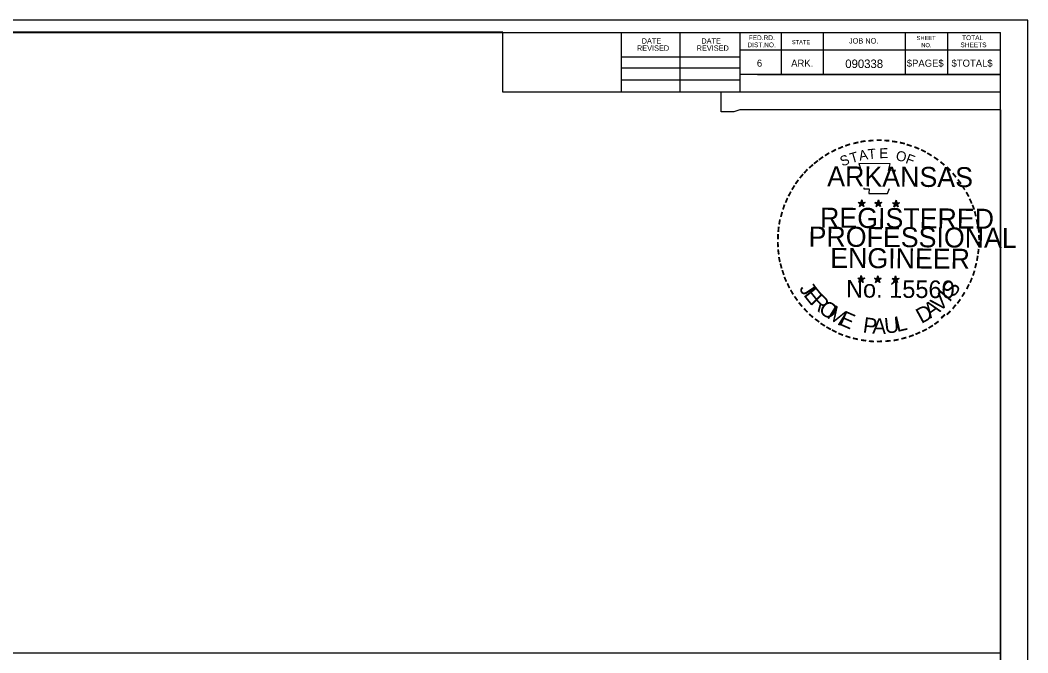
# Model space of a CAD drawing. Extents: x -1.3 to 32.1, y -0.2 to 20.7.
# Drawn here: x 15.42 to 32.07, y 10.29 to 20.75 of the extents above; entities that cross this region are included whole.
import ezdxf

# ---------------------------------------------------------------- set-up
doc = ezdxf.new("R2010")
doc.units = 0
for name, color, linetype in [('Level 1', 7, 'Continuous'), ('Level 24', 7, 'Continuous'), ('Level 62', 7, 'Continuous'), ('Level 63', 7, 'Continuous'), ('Level 63 Full', 7, 'Continuous'), ('R_Border', 7, 'Continuous')]:
    doc.layers.add(name, color=color, linetype=linetype)

msp = doc.modelspace()

# ---------------------------------------------------------------- linework, layer by layer
at = {"layer": 'Level 1'}
for p, q in [((-0.001, 20.545), (31.617, 20.545)), ((25.353, 19.557), (25.353, 20.545)), ((26.321, 19.557), (26.321, 20.545)), ((27.307, 20.545), (27.307, 19.557)), ((27.991, 20.545), (27.991, 19.851)), ((28.685, 20.545), (28.685, 19.851)), ((30.043, 20.545), (30.043, 19.851)), ((30.737, 20.545), (30.737, 19.851)), ((31.617, -0.001), (31.617, 20.545)), ((25.353, 20.143), (27.307, 20.143)), ((31.617, 20.251), (27.307, 20.251)), ((31.617, 20.253), (31.617, 20.253)), ((25.353, 19.957), (27.307, 19.957)), ((31.617, 19.851), (27.307, 19.851)), ((27.603, 19.851), (31.617, 19.851)), ((25.353, 19.763), (27.307, 19.763)), ((31.617, 19.557), (25.353, 19.557))]:
    msp.add_line(p, q, dxfattribs=at)
at = {"layer": 'Level 24'}
for p, q in [((23.392, 20.546), (0, 20.546)), ((23.392, 19.558), (23.392, 20.546)), ((27, 19.558), (23.392, 19.558)), ((27, 19.233), (27, 19.558)), ((27.212, 19.233), (27, 19.233)), ((27.308, 19.266), (27.212, 19.233)), ((31.618, 19.266), (27.308, 19.266)), ((31.618, 10.294), (31.618, 19.266)), ((0, 10.294), (31.618, 10.294))]:
    msp.add_line(p, q, dxfattribs=at)
at = {"layer": 'Level 62'}
for p, q in [((23.392, 20.546), (0, 20.546)), ((23.392, 19.558), (23.392, 20.546)), ((27, 19.558), (23.392, 19.558)), ((27, 19.233), (27, 19.558)), ((27.212, 19.233), (27, 19.233)), ((27.308, 19.266), (27.212, 19.233)), ((31.618, 19.266), (27.308, 19.266)), ((31.618, 10.294), (31.618, 19.266)), ((31.618, 0), (31.618, 10.294))]:
    msp.add_line(p, q, dxfattribs=at)
at = {"layer": 'Level 63'}
msp.add_lwpolyline([(-1.263, -0.2), (32.067, -0.2), (32.067, 20.746), (-1.263, 20.746)], close=True, dxfattribs=at)
at = {"layer": 'Level 63 Full'}
for p, q in [((29.264, 17.735), (29.323, 17.717)), ((29.264, 17.735), (29.307, 17.733)), ((29.264, 17.735), (29.307, 17.731)), ((29.264, 17.735), (29.302, 17.725)), ((29.264, 17.735), (29.302, 17.719)), ((29.264, 17.735), (29.302, 17.717)), ((29.264, 17.735), (29.302, 17.711)), ((29.288, 17.668), (29.323, 17.717)), ((29.288, 17.668), (29.302, 17.715)), ((29.288, 17.668), (29.307, 17.709)), ((29.288, 17.668), (29.309, 17.707)), ((29.288, 17.668), (29.315, 17.703)), ((29.288, 17.668), (29.323, 17.703)), ((29.288, 17.668), (29.323, 17.699)), ((29.323, 17.78), (29.315, 17.735)), ((29.323, 17.78), (29.315, 17.739)), ((29.323, 17.78), (29.319, 17.739)), ((29.323, 17.717), (29.323, 17.78)), ((29.323, 17.78), (29.333, 17.735)), ((29.323, 17.78), (29.331, 17.739)), ((29.323, 17.78), (29.325, 17.739)), ((29.38, 17.735), (29.323, 17.717)), ((29.358, 17.666), (29.323, 17.717)), ((29.358, 17.666), (29.323, 17.703)), ((29.358, 17.666), (29.323, 17.699)), ((29.38, 17.735), (29.327, 17.731)), ((29.358, 17.666), (29.327, 17.703)), ((29.38, 17.735), (29.333, 17.727)), ((29.38, 17.735), (29.333, 17.723)), ((29.358, 17.666), (29.333, 17.715)), ((29.358, 17.666), (29.333, 17.709)), ((29.358, 17.666), (29.339, 17.717)), ((29.38, 17.735), (29.341, 17.723)), ((29.38, 17.735), (29.347, 17.719)), ((29.38, 17.735), (29.349, 17.717)), ((29.539, 17.733), (29.598, 17.717)), ((29.539, 17.733), (29.582, 17.731)), ((29.539, 17.733), (29.582, 17.727)), ((29.539, 17.733), (29.582, 17.725)), ((29.539, 17.733), (29.58, 17.717)), ((29.539, 17.733), (29.58, 17.715)), ((29.539, 17.733), (29.58, 17.709)), ((29.564, 17.666), (29.598, 17.717)), ((29.564, 17.666), (29.582, 17.711)), ((29.564, 17.666), (29.582, 17.709)), ((29.564, 17.666), (29.584, 17.707)), ((29.564, 17.666), (29.59, 17.701)), ((29.564, 17.666), (29.598, 17.701)), ((29.564, 17.666), (29.598, 17.699)), ((29.598, 17.776), (29.59, 17.733)), ((29.598, 17.776), (29.59, 17.735)), ((29.598, 17.776), (29.592, 17.735)), ((29.598, 17.717), (29.598, 17.776)), ((29.598, 17.776), (29.608, 17.733)), ((29.598, 17.776), (29.606, 17.735)), ((29.598, 17.776), (29.6, 17.735)), ((29.655, 17.733), (29.598, 17.717)), ((29.633, 17.666), (29.598, 17.717)), ((29.633, 17.666), (29.598, 17.701)), ((29.633, 17.666), (29.598, 17.699)), ((29.655, 17.733), (29.604, 17.731)), ((29.633, 17.666), (29.604, 17.701)), ((29.655, 17.733), (29.608, 17.725)), ((29.655, 17.733), (29.608, 17.723)), ((29.633, 17.666), (29.608, 17.715)), ((29.633, 17.666), (29.608, 17.707)), ((29.633, 17.666), (29.615, 17.715)), ((29.655, 17.733), (29.617, 17.719)), ((29.655, 17.733), (29.623, 17.717)), ((29.655, 17.733), (29.625, 17.715)), ((29.831, 17.731), (29.89, 17.711)), ((29.831, 17.731), (29.878, 17.725)), ((29.831, 17.731), (29.874, 17.723)), ((29.831, 17.731), (29.874, 17.719)), ((29.831, 17.731), (29.872, 17.715)), ((29.831, 17.731), (29.872, 17.709)), ((29.831, 17.731), (29.872, 17.709)), ((29.853, 17.664), (29.89, 17.711)), ((29.853, 17.664), (29.874, 17.709)), ((29.853, 17.664), (29.878, 17.703)), ((29.853, 17.664), (29.878, 17.701)), ((29.853, 17.664), (29.89, 17.701)), ((29.853, 17.664), (29.886, 17.699)), ((29.853, 17.664), (29.894, 17.692)), ((29.89, 17.772), (29.88, 17.733)), ((29.89, 17.772), (29.886, 17.731)), ((29.89, 17.772), (29.886, 17.731)), ((29.89, 17.711), (29.89, 17.772)), ((29.89, 17.772), (29.902, 17.731)), ((29.89, 17.772), (29.898, 17.731)), ((29.89, 17.772), (29.894, 17.731)), ((29.947, 17.731), (29.89, 17.711)), ((29.923, 17.664), (29.89, 17.711)), ((29.923, 17.664), (29.89, 17.701)), ((29.923, 17.664), (29.89, 17.692)), ((29.947, 17.731), (29.896, 17.725)), ((29.923, 17.664), (29.896, 17.699)), ((29.947, 17.731), (29.902, 17.723)), ((29.947, 17.731), (29.902, 17.717)), ((29.923, 17.664), (29.902, 17.709)), ((29.923, 17.664), (29.902, 17.703)), ((29.923, 17.664), (29.906, 17.709)), ((29.947, 17.731), (29.91, 17.715)), ((29.947, 17.731), (29.912, 17.715)), ((29.947, 17.731), (29.919, 17.711)), ((29.256, 16.483), (29.315, 16.464)), ((29.256, 16.483), (29.298, 16.481)), ((29.256, 16.483), (29.296, 16.475)), ((29.256, 16.483), (29.296, 16.475)), ((29.256, 16.483), (29.296, 16.466)), ((29.256, 16.483), (29.296, 16.464)), ((29.256, 16.483), (29.296, 16.462)), ((29.315, 16.528), (29.302, 16.487)), ((29.315, 16.528), (29.307, 16.483)), ((29.315, 16.528), (29.309, 16.483)), ((29.315, 16.464), (29.315, 16.528)), ((29.315, 16.528), (29.323, 16.483)), ((29.315, 16.528), (29.323, 16.483)), ((29.315, 16.528), (29.315, 16.483)), ((29.372, 16.483), (29.315, 16.464)), ((29.372, 16.483), (29.319, 16.481)), ((29.372, 16.483), (29.323, 16.475)), ((29.372, 16.483), (29.323, 16.473)), ((29.372, 16.483), (29.331, 16.471)), ((29.372, 16.483), (29.335, 16.466)), ((29.372, 16.483), (29.339, 16.464)), ((29.531, 16.483), (29.59, 16.464)), ((29.531, 16.483), (29.574, 16.479)), ((29.531, 16.483), (29.574, 16.475)), ((29.531, 16.483), (29.574, 16.473)), ((29.531, 16.483), (29.572, 16.466)), ((29.531, 16.483), (29.572, 16.462)), ((29.531, 16.483), (29.572, 16.458)), ((29.59, 16.524), (29.58, 16.483)), ((29.59, 16.524), (29.582, 16.483)), ((29.59, 16.524), (29.584, 16.483)), ((29.59, 16.464), (29.59, 16.524)), ((29.59, 16.524), (29.598, 16.481)), ((29.59, 16.524), (29.598, 16.481)), ((29.59, 16.524), (29.59, 16.483)), ((29.645, 16.481), (29.59, 16.464)), ((29.645, 16.481), (29.596, 16.481)), ((29.645, 16.481), (29.598, 16.473)), ((29.645, 16.481), (29.598, 16.473)), ((29.645, 16.481), (29.606, 16.466)), ((29.645, 16.481), (29.613, 16.464)), ((29.645, 16.481), (29.615, 16.462)), ((29.882, 16.522), (29.872, 16.479)), ((29.882, 16.522), (29.874, 16.479)), ((29.882, 16.522), (29.878, 16.479)), ((29.882, 16.458), (29.882, 16.522)), ((29.882, 16.522), (29.89, 16.479)), ((29.882, 16.522), (29.89, 16.479)), ((29.882, 16.522), (29.882, 16.479)), ((29.276, 16.42), (29.315, 16.464)), ((29.276, 16.42), (29.296, 16.464)), ((29.276, 16.42), (29.298, 16.456)), ((29.276, 16.42), (29.3, 16.456)), ((29.276, 16.42), (29.315, 16.454)), ((29.276, 16.42), (29.307, 16.45)), ((29.276, 16.42), (29.315, 16.448)), ((29.347, 16.415), (29.311, 16.448)), ((29.347, 16.415), (29.315, 16.464)), ((29.347, 16.415), (29.315, 16.45)), ((29.347, 16.415), (29.317, 16.45)), ((29.347, 16.415), (29.323, 16.464)), ((29.347, 16.415), (29.323, 16.456)), ((29.347, 16.415), (29.331, 16.464)), ((29.551, 16.415), (29.59, 16.464)), ((29.551, 16.415), (29.574, 16.462)), ((29.551, 16.415), (29.574, 16.454)), ((29.551, 16.415), (29.576, 16.454)), ((29.551, 16.415), (29.582, 16.45)), ((29.551, 16.415), (29.59, 16.45)), ((29.551, 16.415), (29.59, 16.446)), ((29.623, 16.415), (29.588, 16.446)), ((29.623, 16.415), (29.59, 16.464)), ((29.623, 16.415), (29.59, 16.45)), ((29.623, 16.415), (29.592, 16.45)), ((29.623, 16.415), (29.598, 16.462)), ((29.623, 16.415), (29.598, 16.456)), ((29.623, 16.415), (29.606, 16.462)), ((29.823, 16.479), (29.882, 16.458)), ((29.823, 16.479), (29.866, 16.475)), ((29.823, 16.479), (29.866, 16.471)), ((29.823, 16.479), (29.863, 16.466)), ((29.823, 16.479), (29.863, 16.462)), ((29.823, 16.479), (29.861, 16.458)), ((29.823, 16.479), (29.861, 16.454)), ((29.845, 16.411), (29.882, 16.458)), ((29.845, 16.411), (29.863, 16.458)), ((29.845, 16.411), (29.866, 16.45)), ((29.845, 16.411), (29.87, 16.45)), ((29.845, 16.411), (29.874, 16.446)), ((29.845, 16.411), (29.88, 16.446)), ((29.845, 16.411), (29.882, 16.442)), ((29.914, 16.411), (29.88, 16.446)), ((29.914, 16.411), (29.88, 16.442)), ((29.939, 16.479), (29.882, 16.458)), ((29.914, 16.411), (29.882, 16.458)), ((29.914, 16.411), (29.886, 16.446)), ((29.939, 16.479), (29.888, 16.475)), ((29.939, 16.479), (29.89, 16.471)), ((29.939, 16.479), (29.89, 16.466)), ((29.914, 16.411), (29.89, 16.45)), ((29.914, 16.411), (29.894, 16.458)), ((29.914, 16.411), (29.896, 16.458)), ((29.939, 16.479), (29.902, 16.464)), ((29.939, 16.479), (29.904, 16.458)), ((29.939, 16.479), (29.906, 16.458))]:
    msp.add_line(p, q, dxfattribs=at)
for points in [[(29.276, 18.378), (29.317, 18.239)], [(29.855, 18.221), (29.88, 18.27), (29.764, 18.264), (29.79, 18.374), (29.276, 18.378)], [(29.356, 17.976), (29.356, 17.96), (29.447, 17.958), (29.439, 17.882), (29.747, 17.88), (29.78, 17.966)], [(29.323, 17.78), (29.358, 17.666), (29.264, 17.735), (29.38, 17.735), (29.288, 17.668), (29.323, 17.78)], [(29.598, 17.776), (29.633, 17.666), (29.539, 17.733), (29.655, 17.733), (29.564, 17.666), (29.598, 17.776)], [(29.89, 17.772), (29.923, 17.664), (29.831, 17.731), (29.947, 17.731), (29.853, 17.664), (29.89, 17.772)], [(29.315, 16.528), (29.347, 16.415), (29.256, 16.483), (29.372, 16.483), (29.276, 16.42), (29.315, 16.528)], [(29.59, 16.524), (29.623, 16.415), (29.531, 16.483), (29.645, 16.481), (29.551, 16.415), (29.59, 16.524)], [(29.882, 16.522), (29.914, 16.411), (29.823, 16.479), (29.939, 16.479), (29.845, 16.411), (29.882, 16.522)], [(30.647, 15.816), (30.639, 15.842), (30.688, 15.883)], [(30.684, 15.889), (30.692, 15.865), (30.643, 15.822)], [(30.692, 15.869), (30.643, 15.826)], [(30.692, 15.865), (30.645, 15.824)]]:
    msp.add_lwpolyline(points, dxfattribs=at)
for centre, radius in [((29.324, 17.716), 0.0285), ((29.324, 17.716), 0.0258), ((29.324, 17.716), 0.0239), ((29.324, 17.716), 0.0219), ((29.324, 17.716), 0.0191), ((29.324, 17.716), 0.0178), ((29.324, 17.716), 0.0164), ((29.324, 17.716), 0.0141), ((29.324, 17.716), 0.0124), ((29.324, 17.716), 0.0103), ((29.324, 17.716), 0.00819), ((29.324, 17.716), 0.00611), ((29.324, 17.716), 0.0049), ((29.324, 17.716), 0.00238), ((29.6, 17.714), 0.0285), ((29.6, 17.714), 0.0258), ((29.6, 17.714), 0.0239), ((29.6, 17.714), 0.0219), ((29.6, 17.714), 0.0191), ((29.6, 17.714), 0.0178), ((29.6, 17.714), 0.0164), ((29.6, 17.714), 0.0141), ((29.6, 17.714), 0.0124), ((29.6, 17.714), 0.0103), ((29.6, 17.714), 0.00819), ((29.6, 17.714), 0.00611), ((29.6, 17.714), 0.0049), ((29.6, 17.714), 0.00238), ((29.892, 17.71), 0.0285), ((29.892, 17.71), 0.0258), ((29.892, 17.71), 0.0239), ((29.892, 17.71), 0.0219), ((29.892, 17.71), 0.0191), ((29.892, 17.71), 0.0178), ((29.892, 17.71), 0.0164), ((29.892, 17.71), 0.0141), ((29.892, 17.71), 0.0124), ((29.892, 17.71), 0.0103), ((29.892, 17.71), 0.00819), ((29.892, 17.71), 0.00611), ((29.892, 17.71), 0.0049), ((29.892, 17.71), 0.00238), ((29.315, 16.464), 0.0285), ((29.315, 16.464), 0.0258), ((29.315, 16.464), 0.0239), ((29.315, 16.464), 0.0219), ((29.315, 16.464), 0.0191), ((29.315, 16.464), 0.0178), ((29.315, 16.464), 0.0164), ((29.59, 16.462), 0.0285), ((29.59, 16.462), 0.0258), ((29.59, 16.462), 0.0239), ((29.59, 16.462), 0.0219), ((29.59, 16.462), 0.0191), ((29.882, 16.458), 0.0285), ((29.882, 16.458), 0.0258), ((29.882, 16.458), 0.0239), ((29.315, 16.464), 0.0141), ((29.315, 16.464), 0.0124), ((29.315, 16.464), 0.0103), ((29.315, 16.464), 0.00819), ((29.315, 16.464), 0.00611), ((29.315, 16.464), 0.0049), ((29.315, 16.464), 0.00238), ((29.59, 16.462), 0.0178), ((29.59, 16.462), 0.0164), ((29.59, 16.462), 0.0141), ((29.59, 16.462), 0.0124), ((29.59, 16.462), 0.0103), ((29.59, 16.462), 0.00819), ((29.59, 16.462), 0.00611), ((29.59, 16.462), 0.0049), ((29.59, 16.462), 0.00238), ((29.882, 16.458), 0.0219), ((29.882, 16.458), 0.0191), ((29.882, 16.458), 0.0178), ((29.882, 16.458), 0.0164), ((29.882, 16.458), 0.0141), ((29.882, 16.458), 0.0124), ((29.882, 16.458), 0.0103), ((29.882, 16.458), 0.00819), ((29.882, 16.458), 0.00611), ((29.882, 16.458), 0.0049), ((29.882, 16.458), 0.00238)]:
    msp.add_circle(centre, radius, dxfattribs=at)

# ---------------------------------------------------------------- texts
at = {"layer": 'Level 1'}
for s, height, p in [('FED.RD.', 0.0782, (27.455, 20.417)), ('SHEET', 0.0684, (30.229, 20.417)), ('TOTAL', 0.0782, (30.981, 20.417)), ('REVISED', 0.0879, (25.609, 20.241)), ('DATE', 0.0879, (25.687, 20.359)), ('REVISED', 0.0879, (26.595, 20.241)), ('DATE', 0.0879, (26.673, 20.359)), ('DIST.NO.', 0.0782, (27.435, 20.299)), ('STATE', 0.0684, (28.167, 20.349)), ('JOB NO.', 0.0879, (29.112, 20.36)), ('NO.', 0.0684, (30.307, 20.299)), ('SHEETS', 0.0782, (30.953, 20.299)), ('6', 0.117, (27.591, 19.977)), ('ARK.', 0.1172, (28.157, 19.977)), ('090338', 0.14, (29.051, 19.956)), ('$PAGE$', 0.1172, (30.067, 19.977)), ('$TOTAL$', 0.1172, (30.806, 19.977))]:
    msp.add_text(s, height=height, dxfattribs=at).set_placement(p)
at = {"layer": 'Level 63 Full'}
for s, height, rotation, p in [('-', 0.264, 23.9096, (28.962, 18.523)), ('-', 0.264, 18.7785, (29.068, 18.568)), ('-', 0.264, 13.2326, (29.192, 18.606)), ('-', 0.264, 9.8217, (29.302, 18.633)), ('-', 0.264, 5.4992, (29.425, 18.649)), ('-', 0.264, 359.7886, (29.551, 18.661)), ('-', 0.264, 357.3454, (29.674, 18.657)), ('-', 0.264, 351.7641, (29.794, 18.647)), ('-', 0.264, 346.8073, (29.914, 18.629)), ('-', 0.264, 341.9386, (30.019, 18.6)), ('-', 0.264, 337.4575, (30.139, 18.564)), ('-', 0.264, 35.8341, (28.662, 18.347)), ('-', 0.264, 33.666, (28.758, 18.413)), ('-', 0.264, 28.3942, (28.858, 18.472)), ('S', 0.165, 21.1964, (29.001, 18.327)), ('T', 0.165, 16.006, (29.152, 18.382)), ('A', 0.165, 10.8156, (29.29, 18.423)), ('T', 0.165, 5.6252, (29.431, 18.449)), ('E', 0.165, 0.4347, (29.613, 18.466)), ('O', 0.165, 350.0539, (29.878, 18.431)), ('F', 0.165, 339.6731, (30.035, 18.39)), ('-', 0.264, 333.7235, (30.245, 18.521)), ('-', 0.264, 329.2433, (30.339, 18.472)), ('-', 0.264, 325.4651, (30.445, 18.409)), ('-', 0.264, 42.5646, (28.511, 18.217)), ('-', 0.264, 38.5531, (28.584, 18.284)), ('ARKANSAS', 0.3306, 359.6024, (28.752, 18.003)), ('-', 0.264, 320.1321, (30.545, 18.339)), ('-', 0.264, 315.181, (30.645, 18.258)), ('-', 0.264, 50.2166, (28.368, 18.06)), ('-', 0.264, 48.0254, (28.435, 18.139)), ('-', 0.264, 309.4821, (30.737, 18.166)), ('-', 0.264, 57.673, (28.246, 17.876)), ('-', 0.264, 53.8349, (28.299, 17.966)), ('-', 0.264, 306.2546, (30.82, 18.066)), ('-', 0.231, 303.2777, (30.902, 17.97)), ('-', 0.264, 67.3767, (28.152, 17.676)), ('-', 0.264, 62.4738, (28.195, 17.776)), ('-', 0.264, 299.2708, (30.953, 17.87)), ('-', 0.264, 71.9969, (28.113, 17.572)), ('REGISTERED', 0.3306, 359.6024, (28.633, 17.319)), ('-', 0.264, 294.2652, (31.006, 17.768)), ('-', 0.264, 290.1752, (31.051, 17.676)), ('-', 0.264, 75.0634, (28.081, 17.454)), ('-', 0.264, 284.7257, (31.085, 17.578)), ('-', 0.264, 84.7887, (28.044, 17.223)), ('-', 0.264, 80.8037, (28.056, 17.338)), ('PROFESSIONAL', 0.33055, 359.6024, (28.444, 17.007)), ('-', 0.264, 280.1517, (31.118, 17.454)), ('-', 0.264, 276.1986, (31.147, 17.327)), ('-', 0.264, 88.6646, (28.04, 17.107)), ('-', 0.264, 273.9325, (31.155, 17.207)), ('-', 0.264, 93.7983, (28.044, 16.987)), ('ENGINEER', 0.3306, 359.6024, (28.801, 16.654)), ('-', 0.264, 269.5431, (31.159, 17.105)), ('-', 0.264, 98.5503, (28.056, 16.874)), ('-', 0.264, 101.3173, (28.074, 16.754)), ('-', 0.264, 260.5977, (31.141, 16.887)), ('-', 0.264, 263.1196, (31.155, 16.995)), ('-', 0.264, 105.0602, (28.103, 16.656)), ('-', 0.264, 255.365, (31.122, 16.774)), ('-', 0.264, 108.6898, (28.138, 16.554)), ('-', 0.264, 113.6667, (28.178, 16.452)), ('-', 0.264, 247.4911, (31.057, 16.542)), ('-', 0.264, 252.4705, (31.094, 16.654)), ('-', 0.264, 115.3313, (28.229, 16.35)), ('J', 0.255, 303.9209, (28.28, 16.311)), ('E', 0.255, 308.618, (28.351, 16.204)), ('No. 15560', 0.2909, 359.6024, (29.062, 16.165)), ('S', 0.255, 53.5227, (30.835, 16.149)), ('-', 0.264, 244.2221, (31.01, 16.44)), ('-', 0.264, 120.0495, (28.287, 16.252)), ('-', 0.264, 125.4958, (28.354, 16.16)), ('R', 0.255, 314.7784, (28.458, 16.074)), ('V', 0.255, 41.4844, (30.603, 15.916)), ('I', 0.255, 49.9999, (30.772, 16.076)), ('-', 0.264, 238.6736, (30.945, 16.318)), ('-', 0.264, 130.3205, (28.427, 16.069)), ('-', 0.264, 133.8262, (28.513, 15.979)), ('O', 0.255, 321.6761, (28.593, 15.943)), ('M', 0.255, 328.1357, (28.734, 15.836)), ('D', 0.255, 28.5809, (30.307, 15.726)), ('A', 0.255, 34.8903, (30.457, 15.811)), ('-', 0.264, 233.4476, (30.804, 16.12)), ('-', 0.264, 233.4476, (30.881, 16.209)), ('-', 0.264, 138.5362, (28.597, 15.901)), ('-', 0.264, 144.2487, (28.693, 15.834)), ('E', 0.255, 336.4966, (28.931, 15.722)), ('P', 0.255, 351.9783, (29.332, 15.59)), ('A', 0.255, 357.9896, (29.495, 15.569)), ('U', 0.255, 5.7635, (29.708, 15.568)), ('L', 0.255, 13.0992, (29.906, 15.592)), ('-', 0.264, 225.3677, (30.726, 16.024)), ('-', 0.264, 147.6922, (28.782, 15.771)), ('-', 0.264, 151.1728, (28.876, 15.718)), ('-', 0.264, 206.9592, (30.367, 15.742)), ('-', 0.264, 211.8515, (30.459, 15.799)), ('-', 0.264, 215.3387, (30.547, 15.863)), ('-', 0.264, 154.2026, (28.966, 15.675)), ('-', 0.264, 158.1636, (29.068, 15.63)), ('-', 0.264, 162.4007, (29.182, 15.595)), ('-', 0.264, 167.1579, (29.298, 15.569)), ('-', 0.264, 190.8882, (29.929, 15.573)), ('-', 0.264, 195.0767, (30.049, 15.606)), ('-', 0.264, 200.3208, (30.161, 15.646)), ('-', 0.264, 203.854, (30.263, 15.691)), ('-', 0.264, 172.7179, (29.425, 15.55)), ('-', 0.264, 176.1207, (29.549, 15.538)), ('-', 0.264, 181.1942, (29.672, 15.542)), ('-', 0.264, 185.4191, (29.806, 15.553))]:
    msp.add_text(s, height=height, rotation=rotation, dxfattribs=at).set_placement(p)
at = {"layer": 'R_Border'}
msp.add_text('JOB NO.', height=0.0879, dxfattribs=at).set_placement((29.112, 20.36))

doc.saveas('drawing.dxf')
